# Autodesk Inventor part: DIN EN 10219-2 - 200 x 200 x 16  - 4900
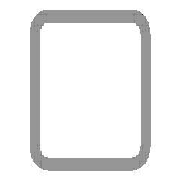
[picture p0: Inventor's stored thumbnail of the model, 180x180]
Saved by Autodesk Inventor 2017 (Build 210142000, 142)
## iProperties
IsCustomPart: 1
Created: 2017-11
Part Number: DIN EN 10219-2 - 200 x 200 x 16  - 4900
Material: Steel, Mild
Description: Cold formed welded structural hollow sections of non-alloy and fine grain structural steel
Document SubType Name: Modeling
Standard: DIN
Designer: iusti
Standard Revision: 2006-07
Standards Organization: DIN
Language: en-US
Size Designation: 200 x 200 x 16
Categories: <MemberInstance><Categories><Category DisplayName="Structural Shapes" InternalName="089c4875-fa83-4c05-b084-43b9cc11f5ed" Mnemonic="GRDR"><CategoryParameter Dis
Stock Number: 200 x 200 x 16
Density: 7.85 g/cm^3
Appearance: Semi-Polished
Mass: 410700 g
Surface Area: 65611.6 cm^2
Volume: 52318.5 cm^3
_CCFamilyMember: 103
_CCFamilyDisplayName: DIN EN 10219-2 (Square Hollow Section - Cold Formed) - Cold formed welded structural hollow sections of non-alloy and fine grain structural steel
_FrameMemberDoc: Frame Member File
_Version: 15.0.0
_GetPNFromCC: 1
G_L: 4900.000 mm
G_W: 200.000 mm
G_H: 200.000 mm
+3C696B27-B370-4381-981B-8782BFEB3638+CUTDETAIL1: Cut
Author: iusti
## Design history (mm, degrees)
node "Start plane"
node "End plane"
sketch "Sketch"
  geometry: L1 (-100, -52)-(-100, 52); L2 (-52, 100)-(52, 100); L3 (100, 52)-(100, -52); L4 (52, -100)-(-52, -100); L5 (-52, 84)-(52, 84); L6 (84, 52)-(84, -52); L7 (52, -84)-(-52, -84); L8 (-84, -52)-(-84, 52); L9 (0, 293.918)-(0, -293.918) reference; L10 (-293.918, 0)-(293.918, 0) reference; A1 r 48 centre (-52, -52) between (-100, -52) and (-52, -100); A2 r 48 centre (-52, 52) between (-52, 100) and (-100, 52); A3 r 48 centre (52, 52) between (100, 52) and (52, 100); A4 r 48 centre (52, -52) between (52, -100) and (100, -52); A5 r 32 centre (-52, 52) between (-52, 84) and (-84, 52); A6 r 32 centre (52, 52) between (84, 52) and (52, 84); A7 r 32 centre (52, -52) between (52, -84) and (84, -52); A8 r 32 centre (-52, -52) between (-84, -52) and (-52, -84)
  constraints: 16 end point, 16 point on circle, 8 centre point, 8 tangent, 4 parallel, 3 equal radius, 2 perpendicular, 7 other
  dimensions: "d7" = 48 radius of A1 (= G_IR); "d10" = 200 distance between parallel lines of L2 L4 (= G_H); "d11" = 200 distance between parallel lines of L1 L3 (= G_W); "d12" = 16 distance between parallel lines of L3 L6 (= G_T); "d15" = 100 distance between parallel lines of L2 L10 (= 0.5 x d10); "d16" = 100 distance between parallel lines of L9 L3 (= 0.5 x d11)
extrude "Body" new body sketch "Sketch" stored distance "d3" = 4900 (= G_L); taper "d4" = 0 deg
node "Driven Length"
  sketch "Sketch3"
    geometry: L1 (0, 0)-(10, 0) reference
    constraints: 2 end point, 1 horizontal
  workplane "Work Plane3"
  sketch "Sketch4"
    geometry: L1 (-2, 100)-(12, 100) reference; L2 (-2, 5000)-(12, 5000) reference
    dimensions: "d18" = 4900 distance between parallel lines of L1 L2 (derived)
workplane "Work Plane4"
split "Split1"
body "Solid1"
other parameters: "G_W" = 200 [user parameter; used in 1 equation term], "G_H" = 200 [user parameter; used in 1 equation term], "G_T" = 16 [user parameter; used in 1 equation term], "G_IR" = 48 [user parameter; used in 1 equation term], "G_L" = 4900 (= d18) [user parameter; used in 1 equation term], "G_OFFSET_END" = 0 [user parameter; used in 1 equation term], "d17" = 90 deg
